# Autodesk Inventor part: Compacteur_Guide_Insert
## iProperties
Created: 2008-12
Part Number: Compacteur_Guide_Insert
Document SubType Name: Modeling
Designer: claivier
Author: claivier
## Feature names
1. Extrusion1
2. Extrusion2
3. Perçage1 [Hole]
